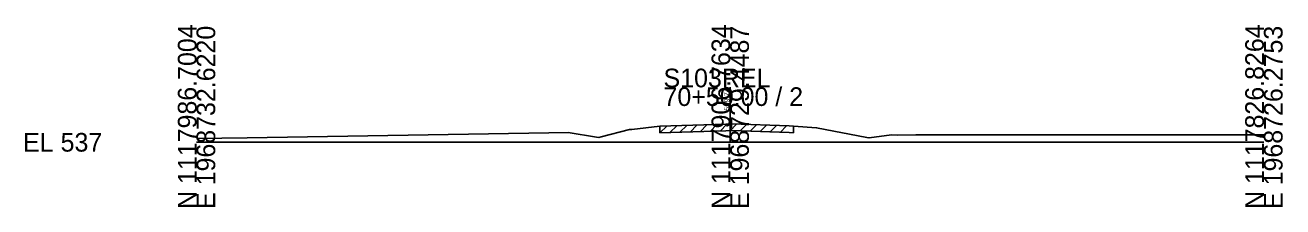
# Model space of a CAD drawing. Extents: x -26 to 163, y -10 to 24518.
# Drawn here: x -25.7 to 162.8, y 18990.3 to 19017.6 of the extents above; entities that cross this region are included whole.
import ezdxf

# ---------------------------------------------------------------- set-up
doc = ezdxf.new("R2010")
doc.units = 0
for name, color, linetype in [('RD_GPK_XS_Cell', 7, 'Continuous'), ('RD_XS_ExGround', 7, 'Continuous'), ('RD_XS_ExPaveRet', 7, 'Continuous'), ('RD_XS_TX_Elev_EX', 7, 'Continuous')]:
    doc.layers.add(name, color=color, linetype=linetype)

msp = doc.modelspace()

# ---------------------------------------------------------------- linework, layer by layer
at = {"layer": 'RD_GPK_XS_Cell'}
for p, q in [((80, 19000), (80, 19008.25)), ((0, 19000), (80, 19000)), ((80, 19000), (160, 19000))]:
    msp.add_line(p, q, dxfattribs=at)
at = {"layer": 'RD_XS_ExGround'}
msp.add_lwpolyline([(0, 19000.58), (7.58, 19000.65), (52.81, 19001.42), (55.72, 19001.46), (59.94, 19000.78), (60.31, 19000.72), (60.64, 19000.81), (64.88, 19001.9), (65.26, 19001.94), (69.47, 19002.4), (79.32, 19002.72), (80.17, 19002.75), (88.83, 19002.45), (89.47, 19002.42), (92.95, 19002.18), (100.46, 19000.73), (100.81, 19000.66), (104.19, 19001.13), (105.12, 19001.09), (107.83, 19001.12), (160, 19001.1)], dxfattribs=at)
at = {"layer": 'RD_XS_ExPaveRet'}
for p, q in [((69.47, 19001.4), (70.5, 19002.43)), ((69.47, 19001.4), (69.47, 19002.4)), ((70.97, 19001.45), (72, 19002.48)), ((72.47, 19001.5), (73.5, 19002.53)), ((73.97, 19001.54), (75, 19002.58)), ((75.47, 19001.59), (76.5, 19002.63)), ((76.97, 19001.64), (78, 19002.68)), ((78.47, 19001.69), (79.5, 19002.73)), ((79.97, 19001.74), (80.95, 19002.72)), ((81.47, 19001.7), (82.44, 19002.67)), ((82.97, 19001.65), (83.94, 19002.62)), ((84.47, 19001.6), (85.44, 19002.57)), ((85.97, 19001.55), (86.94, 19002.51)), ((87.47, 19001.49), (88.44, 19002.46)), ((89.47, 19002.42), (89.47, 19001.42)), ((69.47, 19001.4), (79.32, 19001.72)), ((79.32, 19001.72), (80.17, 19001.75)), ((80.17, 19001.75), (88.83, 19001.45)), ((88.83, 19001.45), (89.47, 19001.42))]:
    msp.add_line(p, q, dxfattribs=at)

# ---------------------------------------------------------------- texts
at = {"layer": 'RD_GPK_XS_Cell'}
for s, p in [('N 1117986.7004', (0, 18990)), ('E 1968732.6220', (2.8, 18990)), ('N 1117906.7634', (80, 18990)), ('E 1968729.4487', (82.8, 18990)), ('N 1117826.8264', (160, 18990)), ('E 1968726.2753', (162.8, 18990))]:
    msp.add_text(s, height=2.8, rotation=90, dxfattribs=at).set_placement(p)
for s, p in [('S103REL', (70, 19008.25)), ('70+50.00 / 2', (70, 19005.45)), ('EL 537', (-26, 18998.6))]:
    msp.add_text(s, height=2.8, dxfattribs=at).set_placement(p)
at = {"layer": 'RD_XS_TX_Elev_EX'}
msp.add_text('539.74', height=0.8, rotation=90, dxfattribs=at).set_placement((79.9, 19004.74))

doc.saveas('drawing.dxf')
